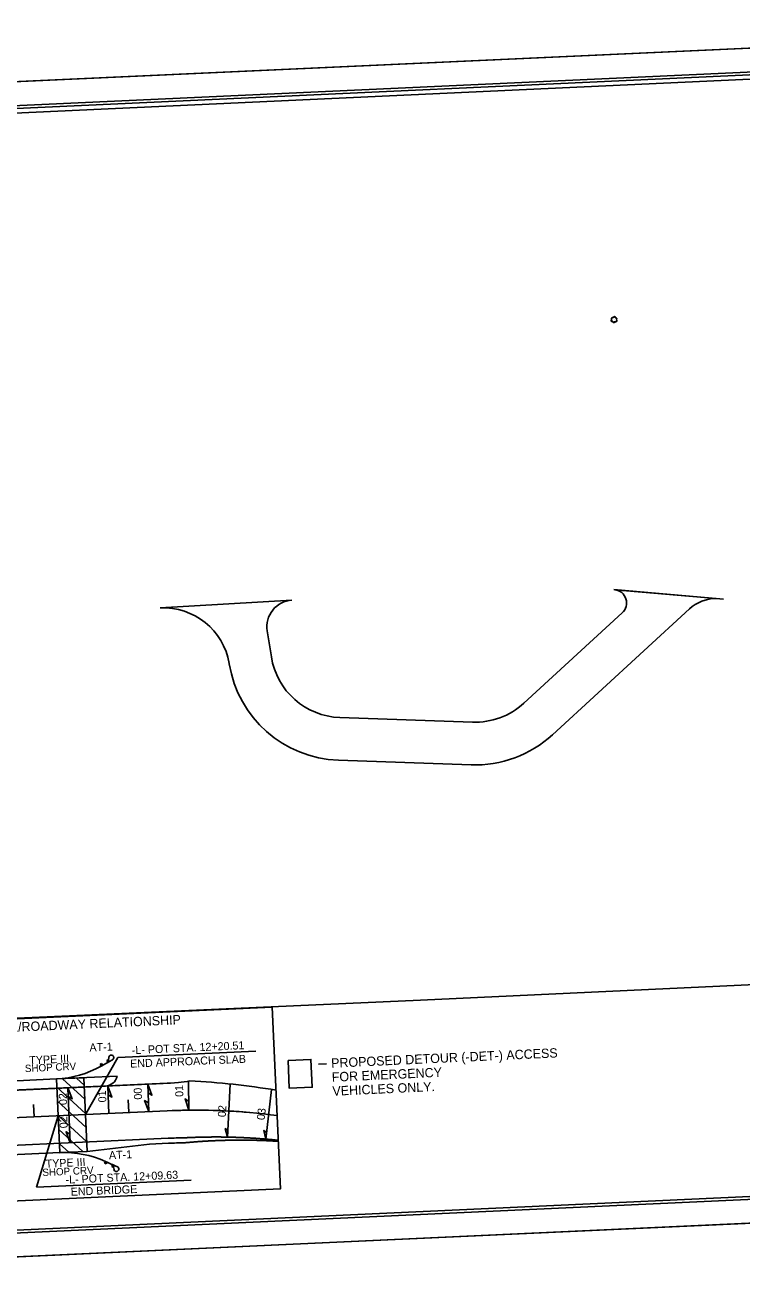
# Model space of a CAD drawing. Extents: x 1191067 to 1191874, y 892813 to 893283.
# Drawn here: x 1191329.2 to 1191598.1, y 892813.1 to 893283.5 of the extents above; entities that cross this region are included whole.
import ezdxf

# ---------------------------------------------------------------- set-up
doc = ezdxf.new("R2010")
doc.units = 0
for name, color, linetype in [('Default', 7, 'Continuous'), ('Prop Approach Slab', 7, 'Continuous'), ('Prop DSN Text', 7, 'Continuous'), ('Prop EOT', 7, 'Continuous'), ('Prop Guardrail Anchor Unit CELL', 7, 'Continuous'), ('Prop Guardrail Shop Curved', 7, 'Continuous'), ('Prop Horizontal Alignment', 7, 'Continuous'), ('Prop Horizontal Alignment Tick Small', 7, 'Continuous'), ('Prop Leader Line Medium', 7, 'Continuous'), ('Prop Paved Shoulder', 7, 'Continuous'), ('Prop Roadway Bridge', 7, 'Continuous'), ('Prop Shade Light', 7, 'Continuous'), ('Prop Superelevation  Arrow CELL', 7, 'Continuous'), ('Prop Superelevation Label', 7, 'Continuous'), ('Sheet Border Standard 30in CELL', 7, 'Continuous'), ('Sheet Clip Boundary CELL', 7, 'Continuous'), ('Sheet Cutting Line CELL', 7, 'Continuous'), ('Sheet Plot Border Inside CELL', 7, 'Continuous'), ('Sheet Plot Border Outside CELL', 7, 'Continuous')]:
    doc.layers.add(name, color=color, linetype=linetype)

msp = doc.modelspace()

# ---------------------------------------------------------------- linework, layer by layer
at = {"layer": 'Default'}
msp.add_line((1191550.19, 893173.01), (1191550.19, 893173.01), dxfattribs=at)
for centre, radius, start, end in [((1191549.47, 893172.73), 0.382, 95.1099, 327.9534), ((1191549.6, 893173.47), 0.387, 35.8908, 245.4216), ((1191550.14, 893172.34), 0.393, 151.2797, 21.387), ((1191550.28, 893173.83), 0.396, 334.8391, 200.4717), ((1191550.85, 893172.64), 0.375, 204.9913, 73.4601), ((1191550.86, 893173.36), 0.372, 284.4567, 126.0861)]:
    msp.add_arc(centre, radius, start, end, dxfattribs=at)
at = {"layer": 'Prop Approach Slab'}
for p, q in [((1191341, 892888.46), (1191351.3, 892888.93)), ((1191351.91, 892875.54), (1191341.14, 892885.37)), ((1191351.67, 892880.84), (1191343.21, 892888.56)), ((1191351.43, 892886.11), (1191348.48, 892888.8)), ((1191351.3, 892888.93), (1191352.56, 892861.31)), ((1191352.16, 892870.25), (1191341.38, 892880.08)), ((1191352.4, 892864.95), (1191341.62, 892874.78)), ((1191350.91, 892861.23), (1191341.87, 892869.48)), ((1191345.61, 892860.99), (1191342.11, 892864.18)), ((1191342.26, 892860.84), (1191352.56, 892861.31))]:
    msp.add_line(p, q, dxfattribs=at)
at = {"layer": 'Prop EOT'}
for p, q in [((1191230.16, 892879.9), (1191385.24, 892887)), ((1191238.44, 892880.25), (1191383.84, 892886.9)), ((1191383.84, 892886.9), (1191385.24, 892887)), ((1191385.24, 892887), (1191386.75, 892887.1)), ((1191239.47, 892859.65), (1191382.94, 892866.22))]:
    msp.add_line(p, q, dxfattribs=at)
for centre, radius, start, end in [((1191359.16, 892890.47), 4.69, 272.6195, 348.142), ((1191383.07, 892925.99), 39.06, 275.3979, 281.7955), ((1191375.43, 892590.39), 297.77, 80.7298, 86.9917), ((1191393.18, 892642.39), 224.06, 91.07, 92.6195)]:
    msp.add_arc(centre, radius, start, end, dxfattribs=at)
msp.add_spline([(1191389, 892866.41), (1191389.6, 892866.44), (1191390.21, 892866.47), (1191390.81, 892866.5), (1191391.42, 892866.52), (1191392.03, 892866.55), (1191392.63, 892866.57), (1191393.24, 892866.59), (1191393.84, 892866.61), (1191394.45, 892866.63), (1191395.06, 892866.64), (1191395.66, 892866.66), (1191396.27, 892866.67), (1191396.88, 892866.68), (1191397.48, 892866.69), (1191398.09, 892866.7), (1191398.7, 892866.7), (1191399.3, 892866.71), (1191399.91, 892866.71), (1191400.52, 892866.71), (1191401.12, 892866.71), (1191401.73, 892866.71), (1191402.34, 892866.71), (1191402.94, 892866.7), (1191403.55, 892866.69), (1191404.16, 892866.69), (1191404.77, 892866.68), (1191405.37, 892866.66), (1191405.98, 892866.65), (1191406.59, 892866.63), (1191407.19, 892866.62), (1191407.8, 892866.6), (1191408.41, 892866.58), (1191409.02, 892866.56), (1191409.62, 892866.53), (1191410.23, 892866.51), (1191410.84, 892866.48), (1191411.45, 892866.45), (1191412.05, 892866.42), (1191412.66, 892866.39), (1191413.27, 892866.36), (1191413.87, 892866.32), (1191414.48, 892866.29), (1191415.09, 892866.25), (1191415.7, 892866.21), (1191416.3, 892866.17), (1191416.91, 892866.12), (1191417.52, 892866.08), (1191418.12, 892866.03), (1191418.73, 892865.98), (1191419.34, 892865.93), (1191419.94, 892865.88), (1191420.55, 892865.83), (1191421.15, 892865.77), (1191421.76, 892865.72), (1191422.37, 892865.66), (1191422.97, 892865.6), (1191423.58, 892865.54), (1191424.18, 892865.48), (1191424.26, 892865.47)], degree=3, dxfattribs=at)
at = {"layer": 'Prop Guardrail Anchor Unit CELL'}
for p, q in [((1191357.94, 892894.25), (1191357.37, 892893.93)), ((1191357.37, 892893.93), (1191357.74, 892893.27)), ((1191358.31, 892893.59), (1191357.37, 892893.93)), ((1191357.74, 892893.27), (1191360.63, 892894.9)), ((1191357.74, 892893.27), (1191357.94, 892894.25)), ((1191358.31, 892893.59), (1191357.94, 892894.25)), ((1191360.43, 892895.65), (1191359.85, 892895.33)), ((1191359.85, 892895.33), (1191360.23, 892894.67)), ((1191360.8, 892894.99), (1191359.85, 892895.33)), ((1191360.23, 892894.67), (1191360.43, 892895.65)), ((1191360.23, 892894.67), (1191360.8, 892894.99)), ((1191360.8, 892894.99), (1191360.43, 892895.65)), ((1191360.66, 892896.61), (1191360.51, 892895.49)), ((1191360.69, 892894.93), (1191360.58, 892894.87)), ((1191360.69, 892894.93), (1191360.58, 892894.87)), ((1191360.63, 892894.9), (1191362.04, 892895.68)), ((1191360.8, 892894.99), (1191360.63, 892895.28)), ((1191360.8, 892894.99), (1191360.63, 892895.28)), ((1191357.74, 892893.27), (1191358.31, 892893.59)), ((1191359.06, 892856.88), (1191359.37, 892857.57)), ((1191359.97, 892857.3), (1191359.06, 892856.88)), ((1191359.66, 892856.61), (1191359.06, 892856.88)), ((1191359.37, 892857.57), (1191362.41, 892856.21)), ((1191359.37, 892857.57), (1191359.97, 892857.3)), ((1191359.37, 892857.57), (1191359.66, 892856.61)), ((1191359.97, 892857.3), (1191359.66, 892856.61)), ((1191361.72, 892855.69), (1191362.03, 892856.38)), ((1191362.03, 892856.38), (1191362.63, 892856.11)), ((1191362.03, 892856.38), (1191362.32, 892855.42)), ((1191362.63, 892856.11), (1191361.72, 892855.69)), ((1191362.32, 892855.42), (1191361.72, 892855.69)), ((1191362.63, 892856.11), (1191362.32, 892855.42)), ((1191362.59, 892854.5), (1191362.36, 892855.5)), ((1191362.52, 892856.16), (1191362.41, 892856.21)), ((1191362.41, 892856.21), (1191363.87, 892855.55)), ((1191362.52, 892856.16), (1191362.41, 892856.21)), ((1191362.63, 892856.11), (1191362.5, 892855.81)), ((1191362.63, 892856.11), (1191362.5, 892855.81))]:
    msp.add_line(p, q, dxfattribs=at)
for centre, major_axis, start_param, end_param in [((1191361.58, 892896.5), (-0.456, 0.812), 3.141593, 7.214552), ((1191363.49, 892854.7), (0.381, 0.85), 2.210226, 6.283185)]:
    msp.add_ellipse(centre, major_axis=major_axis, ratio=0.995379, start_param=start_param, end_param=end_param, dxfattribs=at)
at = {"layer": 'Prop Guardrail Shop Curved'}
for centre, start, end in [((1191339.29, 892925.91), 272.6195, 299.4769), ((1191343.98, 892823.37), 65.7587, 92.6195)]:
    msp.add_arc(centre, 37.5, start, end, dxfattribs=at)
at = {"layer": 'Prop Horizontal Alignment'}
msp.add_line((1191223.93, 892869.26), (1191382.47, 892876.52), dxfattribs=at)
for radius, start in [(234.38, 85.0642), (234.37, 82.4858), (234.37, 82.4858)]:
    msp.add_arc((1191393.18, 892642.39), radius, start, 92.6195, dxfattribs=at)
at = {"layer": 'Prop Horizontal Alignment Tick Small'}
for p, q in [((1191368.13, 892875.97), (1191367.92, 892880.65)), ((1191332.61, 892874.24), (1191332.4, 892878.92)), ((1191332.61, 892874.24), (1191332.4, 892878.92))]:
    msp.add_line(p, q, dxfattribs=at)
at = {"layer": 'Prop Leader Line Medium'}
for p, q in [((1191364.02, 892896.55), (1191415.74, 892898.92)), ((1191351.93, 892875.12), (1191364.02, 892896.55)), ((1191341.63, 892874.65), (1191333.55, 892847.9)), ((1191333.55, 892847.9), (1191391.52, 892850.55))]:
    msp.add_line(p, q, dxfattribs=at)
msp.add_lwpolyline([(1191222.24, 892906.26), (1191421.97, 892915.4), (1191425.09, 892847.28), (1191225.35, 892838.14)], close=True, dxfattribs=at)
at = {"layer": 'Prop Paved Shoulder'}
for p, q in [((1191341, 892888.46), (1191363.75, 892889.5)), ((1191342.26, 892860.84), (1191352.56, 892861.31)), ((1191352.56, 892861.31), (1191375.9, 892864.02)), ((1191375.9, 892864.02), (1191383.03, 892864.34))]:
    msp.add_line(p, q, dxfattribs=at)
msp.add_arc((1191393.18, 892642.39), 222.19, 91.0548, 92.6195, dxfattribs=at)
msp.add_spline([(1191389.03, 892864.54), (1191389.63, 892864.59), (1191390.23, 892864.65), (1191390.83, 892864.7), (1191391.43, 892864.75), (1191392.03, 892864.8), (1191392.64, 892864.85), (1191393.24, 892864.9), (1191393.84, 892864.94), (1191394.44, 892864.98), (1191395.04, 892865.03), (1191395.64, 892865.07), (1191396.25, 892865.1), (1191396.85, 892865.14), (1191397.45, 892865.18), (1191398.06, 892865.21), (1191398.66, 892865.24), (1191399.26, 892865.27), (1191399.87, 892865.3), (1191400.47, 892865.33), (1191401.07, 892865.35), (1191401.68, 892865.38), (1191402.28, 892865.4), (1191402.89, 892865.42), (1191403.49, 892865.44), (1191404.1, 892865.45), (1191404.7, 892865.47), (1191405.31, 892865.48), (1191405.91, 892865.49), (1191406.52, 892865.51), (1191407.13, 892865.51), (1191407.73, 892865.52), (1191408.34, 892865.53), (1191408.94, 892865.53), (1191409.55, 892865.53), (1191410.16, 892865.53), (1191410.76, 892865.53), (1191411.37, 892865.53), (1191411.98, 892865.53), (1191412.58, 892865.52), (1191413.19, 892865.51), (1191413.8, 892865.5), (1191414.41, 892865.49), (1191415.01, 892865.48), (1191415.62, 892865.47), (1191416.23, 892865.45), (1191416.84, 892865.43), (1191417.44, 892865.41), (1191418.05, 892865.39), (1191418.66, 892865.37), (1191419.27, 892865.35), (1191419.87, 892865.32), (1191420.48, 892865.29), (1191421.09, 892865.26), (1191421.7, 892865.23), (1191422.31, 892865.2), (1191422.91, 892865.17), (1191423.52, 892865.13), (1191424.13, 892865.09), (1191424.27, 892865.08)], degree=3, dxfattribs=at)
at = {"layer": 'Prop Roadway Bridge'}
for p, q in [((1191308.22, 892886.96), (1191341, 892888.46)), ((1191341, 892888.46), (1191342.26, 892860.84)), ((1191309.48, 892859.34), (1191342.26, 892860.84))]:
    msp.add_line(p, q, dxfattribs=at)
at = {"layer": 'Prop Shade Light'}
for p, q in [((1191379.88, 893065.01), (1191429.32, 893067.94)), ((1191429.32, 893067.94), (1191379.88, 893065.01)), ((1191550.12, 893071.88), (1191591.25, 893068.33)), ((1191588.5, 893068.56), (1191550.46, 893071.85)), ((1191410.33, 893066.82), (1191410.33, 893066.82)), ((1191527.09, 893017.48), (1191578.45, 893064.62)), ((1191553.24, 893063.2), (1191516.27, 893029.27)), ((1191421.61, 893046.69), (1191420.08, 893056.4)), ((1191497.07, 893022.18), (1191447.33, 893023.92)), ((1191446.78, 893007.93), (1191496.51, 893006.19)), ((1191439.32, 892893.99), (1191442.31, 892894.12))]:
    msp.add_line(p, q, dxfattribs=at)
msp.add_lwpolyline([(1191405.81, 893044.2), (1191405.81, 893044.2)], dxfattribs=at)
msp.add_lwpolyline([(1191427.86, 892895.38), (1191436.47, 892895.77), (1191436.94, 892885.34), (1191428.33, 892884.95)], close=True, dxfattribs=at)
for centre, radius, start, end in [((1191429.95, 893057.96), 10, 93.6582, 188.9764), ((1191549.86, 893066.88), 5, 312.5411, 83.0925), ((1191588.59, 893053.57), 15, 90.3526, 132.5411), ((1191381.15, 893040.04), 25, 9.5636, 92.9116), ((1191448.28, 893050.91), 27, 188.9764, 267.9944), ((1191448.28, 893050.91), 43, 188.9764, 189.1922), ((1191381.15, 893040.04), 25, 9.1923, 9.1924), ((1191448.28, 893050.91), 43, 189.1923, 267.9944), ((1191498.01, 893049.17), 27, 267.9944, 312.5411), ((1191498.01, 893049.17), 43, 267.9944, 312.5411)]:
    msp.add_arc(centre, radius, start, end, dxfattribs=at)
at = {"layer": 'Prop Superelevation  Arrow CELL'}
for p, q in [((1191346.19, 892864.53), (1191345.25, 892885.14)), ((1191360.24, 892885.82), (1191360.71, 892875.52)), ((1191375.69, 892876.21), (1191375.22, 892886.51)), ((1191390.68, 892876.75), (1191390.56, 892887.65)), ((1191405.15, 892866.67), (1191406.22, 892886.57)), ((1191421.72, 892884.54), (1191419.53, 892865.92))]:
    msp.add_line(p, q, dxfattribs=at)
for points in [[(1191345.25, 892885.14), (1191346.85, 892880.99), (1191345.4, 892881.89)], [(1191360.24, 892885.82), (1191361.83, 892881.67), (1191360.38, 892882.57)], [(1191375.22, 892886.51), (1191376.82, 892882.36), (1191375.37, 892883.26)], [(1191375.69, 892876.21), (1191374.09, 892880.36), (1191375.54, 892879.46)], [(1191390.68, 892876.75), (1191389.23, 892880.95), (1191390.65, 892880)], [(1191346.19, 892864.53), (1191344.6, 892868.68), (1191346.05, 892867.78)], [(1191405.15, 892866.67), (1191404.3, 892869.89), (1191405.3, 892869.1)], [(1191419.53, 892865.92), (1191418.85, 892869.18), (1191419.82, 892868.34)]]:
    msp.add_lwpolyline(points, close=True, dxfattribs=at)
at = {"layer": 'Sheet Border Standard 30in CELL'}
msp.add_lwpolyline([(1191783.48, 893273.17), (1191184.11, 893245.75), (1191203.31, 892826.19), (1191802.68, 892853.61)], close=True, dxfattribs=at)
at = {"layer": 'Sheet Clip Boundary CELL'}
msp.add_lwpolyline([(1191202.89, 892905.77), (1191187.26, 893244.08), (1191701.27, 893267.82), (1191704.06, 893207.36), (1191782.86, 893211), (1191795.71, 892932.92), (1191477.62, 892917.95)], close=True, dxfattribs=at)
at = {"layer": 'Sheet Cutting Line CELL'}
for p, q in [((1191789.82, 893283.47), (1191116.92, 893252.68)), ((1191137.03, 892813.14), (1191809.93, 892843.93))]:
    msp.add_line(p, q, dxfattribs=at)
at = {"layer": 'Sheet Plot Border Inside CELL'}
msp.add_lwpolyline([(1191788.43, 893274.42), (1191122.53, 893243.95), (1191141.82, 892822.35), (1191807.72, 892852.82)], close=True, dxfattribs=at)
at = {"layer": 'Sheet Plot Border Outside CELL'}
msp.add_lwpolyline([(1191789.82, 893283.47), (1191116.92, 893252.68), (1191137.03, 892813.14), (1191809.93, 892843.93)], close=True, dxfattribs=at)

# ---------------------------------------------------------------- texts
at = {"layer": 'Default'}
for s, p in [('PROPOSED DETOUR (-DET-) ACCESS ', (1191444.12, 892892.65)), ('FOR EMERGENCY ', (1191444.36, 892887.4)), ('VEHICLES ONLY.', (1191444.6, 892882.16))]:
    msp.add_text(s, height=3.5, rotation=2.6195, dxfattribs=at).set_placement(p)
at = {"layer": 'Prop DSN Text'}
msp.add_text('SKETCH SHOWING BRIDGE/ROADWAY RELATIONSHIP', height=3.5, rotation=2.6195, dxfattribs=at).set_placement((1191264.34, 892903.34))
at = {"layer": 'Prop Guardrail Anchor Unit CELL'}
for s, height, p in [('AT-1', 3, (1191353.44, 892898.73)), ('SHOP CRV', 2.75, (1191329.23, 892891.01)), ('TYPE III', 3, (1191330.87, 892893.95)), ('AT-1', 3, (1191360.76, 892858.37)), ('TYPE III', 3, (1191337.03, 892855.2)), ('SHOP CRV', 2.75, (1191335.78, 892852.04))]:
    msp.add_text(s, height=height, rotation=2.6195, dxfattribs=at).set_placement(p)
at = {"layer": 'Prop Leader Line Medium'}
for s, rotation, p in [('-L- POT STA. 12+20.51', 2.5888, (1191369.34, 892897.73)), ('END APPROACH SLAB', 2.4356, (1191368.71, 892892.69)), ('-L- POT STA. 12+09.63', 2.5888, (1191344.48, 892849.2)), ('END BRIDGE', 2.4356, (1191346.41, 892844.67))]:
    msp.add_text(s, height=3, rotation=rotation, dxfattribs=at).set_placement(p)
at = {"layer": 'Prop Superelevation Label'}
for s, rotation, p in [('00', 92.6195, (1191373.14, 892880.78)), ('01', 91.2991, (1191388.6, 892881.77)), ('02', 92.6195, (1191345.02, 892878.76)), ('01', 92.6195, (1191359.74, 892879.75)), ('02', 86.2228, (1191404.48, 892874.08)), ('03', 83.8593, (1191419.09, 892872.94)), ('02', 92.6195, (1191345.23, 892870.05))]:
    msp.add_text(s, height=3, rotation=rotation, dxfattribs=at).set_placement(p)

doc.saveas('drawing.dxf')
